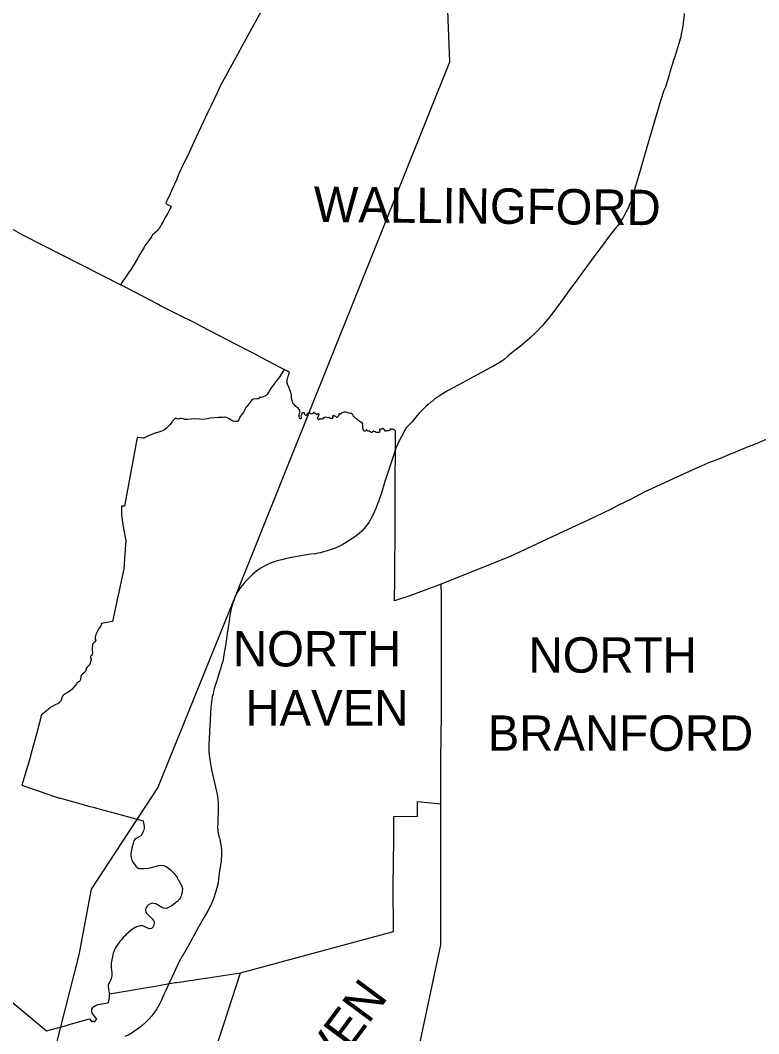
# Model space of a CAD drawing. Extents: x 0 to 2603, y -226 to 830.
# Drawn here: x 163.93 to 192.1, y 536.34 to 575 of the extents above; entities that cross this region are included whole.
import ezdxf

# ---------------------------------------------------------------- set-up
doc = ezdxf.new("R2010")
doc.units = 0
for name, color, linetype in [('CT_TSH_Map_Districts', 7, 'Continuous'), ('CT_TSH_Map_Interstate_Roads', 7, 'Continuous'), ('CT_TSH_Map_Town_Limits', 7, 'Continuous'), ('CT_TSH_Map_Town_Text', 7, 'Continuous'), ('CT_TSH_Map_US_and_State_Routes', 7, 'Continuous')]:
    doc.layers.add(name, color=color, linetype=linetype)

msp = doc.modelspace()

# ---------------------------------------------------------------- linework, layer by layer
at = {"layer": 'CT_TSH_Map_Districts'}
for points in [[(173.233, 575.543), (172.476, 574.159), (172.221, 573.694), (171.56, 572.484), (171.449, 572.255), (171.196, 571.72), (171.085, 571.492), (170.547, 570.342), (170.371, 569.958), (170.259, 569.712), (170.163, 569.522), (169.98, 569.133), (169.95, 569.088), (169.948, 569.08), (169.885, 568.911), (169.81, 568.745), (169.735, 568.578), (169.645, 568.377), (169.54, 568.136), (169.502, 568.052), (169.487, 568.006), (169.576, 567.958), (169.669, 567.907), (169.691, 567.885), (169.614, 567.745), (169.574, 567.663), (169.546, 567.619), (169.518, 567.581), (169.463, 567.478), (169.405, 567.37), (169.323, 567.217), (169.285, 567.144), (169.259, 567.104), (169.235, 567.063), (169.219, 567.041), (169.197, 567.017), (169.169, 566.978), (169.125, 566.935), (169.045, 566.871), (169.009, 566.84), (168.978, 566.813), (168.945, 566.758), (168.837, 566.602), (168.744, 566.483), (168.684, 566.387), (168.644, 566.318), (168.578, 566.21), (168.496, 566.071), (168.405, 565.913), (168.28, 565.693), (168.162, 565.506), (168.058, 565.359), (167.952, 565.205), (167.881, 565.096), (167.829, 565.027), (167.807, 564.99), (167.785, 564.951), (167.779, 564.932), (167.77, 564.908), (167.768, 564.9)], [(163.306, 567.224), (164.016, 566.811), (165.545, 566.034), (167.768, 564.9)]]:
    msp.add_lwpolyline(points, dxfattribs=at)
at = {"layer": 'CT_TSH_Map_Interstate_Roads'}
for p, q in [((189.167, 574.582), (189.157, 574.531)), ((187.871, 570.279), (187.654, 569.539)), ((183.012, 562.568), (182.68, 562.318)), ((179.946, 560.69), (179.877, 560.645)), ((179.073, 559.925), (178.883, 559.677)), ((179.145, 560.01), (179.073, 559.925)), ((178.883, 559.677), (178.655, 559.453)), ((174.356, 554.519), (174.287, 554.506)), ((174.78, 554.589), (174.356, 554.519)), ((171.929, 552.293), (171.893, 552.077)), ((171.547, 550.197), (171.41, 549.761)), ((171.564, 550.252), (171.547, 550.197)), ((171.233, 549.076), (171.207, 548.894)), ((171.149, 547.889), (171.131, 547.561)), ((170.948, 540.793), (170.759, 540.456)), ((168.474, 536.57), (168.438, 536.542))]:
    msp.add_line(p, q, dxfattribs=at)
for points in [[(189.25, 575.254), (189.251, 575.203), (189.234, 575.008), (189.203, 574.777), (189.167, 574.582)], [(189.157, 574.531), (189.109, 574.309), (189.086, 574.239)], [(189.086, 574.239), (188.881, 573.557), (188.853, 573.497)], [(188.853, 573.497), (188.825, 573.383), (188.763, 573.185), (188.708, 573.012)], [(188.708, 573.012), (188.678, 572.909), (188.537, 572.445)], [(188.537, 572.445), (188.483, 572.315), (188.355, 571.926), (187.871, 570.279)], [(187.654, 569.539), (187.521, 569.082), (187.398, 568.668), (187.277, 568.245), (187.227, 568.101), (187.161, 567.937), (187.101, 567.8), (187.044, 567.688), (186.981, 567.572), (186.912, 567.453)], [(186.912, 567.453), (186.845, 567.347), (186.813, 567.3), (186.732, 567.186), (186.64, 567.063), (186.544, 566.947), (186.498, 566.893), (186.398, 566.759), (186.126, 566.391), (185.853, 566.022), (185.569, 565.64), (185.395, 565.403)], [(185.395, 565.403), (185.355, 565.35), (185.093, 564.996)], [(185.093, 564.996), (184.923, 564.767), (184.469, 564.147)], [(184.469, 564.147), (184.347, 563.975), (184.248, 563.839), (184.06, 563.598), (183.847, 563.354), (183.613, 563.104), (183.367, 562.872), (183.194, 562.719), (183.012, 562.568)], [(182.68, 562.318), (182.609, 562.249), (182.531, 562.182), (182.385, 562.063), (182.262, 561.975), (182.131, 561.89), (181.987, 561.809), (181.81, 561.719), (181.686, 561.655), (181.199, 561.387), (180.918, 561.237)], [(180.918, 561.237), (180.64, 561.085), (180.227, 560.861)], [(180.227, 560.861), (180.125, 560.801), (180.027, 560.738), (179.946, 560.69)], [(179.65, 560.474), (179.605, 560.442), (179.488, 560.343)], [(179.877, 560.645), (179.845, 560.619), (179.728, 560.539), (179.65, 560.474)], [(179.488, 560.343), (179.391, 560.256), (179.337, 560.202), (179.246, 560.107), (179.145, 560.01)], [(178.655, 559.453), (178.591, 559.348), (178.524, 559.216), (178.463, 559.1), (178.395, 558.975), (178.33, 558.841), (178.259, 558.674), (178.184, 558.438), (177.916, 557.636), (177.842, 557.402), (177.692, 556.925), (177.637, 556.755), (177.607, 556.663), (177.563, 556.554), (177.491, 556.379), (177.432, 556.234), (177.371, 556.096), (177.309, 555.984), (177.223, 555.847), (177.139, 555.728), (177.051, 555.618), (176.959, 555.516), (176.856, 555.421), (176.745, 555.331), (176.679, 555.288)], [(176.679, 555.288), (176.456, 555.137), (176.358, 555.076), (176.23, 555.006), (176.078, 554.929), (175.941, 554.868), (175.795, 554.81), (175.674, 554.77)], [(175.28, 554.668), (175.188, 554.651), (175.02, 554.628), (174.78, 554.589)], [(175.674, 554.77), (175.601, 554.748), (175.503, 554.719), (175.38, 554.688), (175.28, 554.668)], [(173.633, 554.34), (173.58, 554.324), (173.48, 554.287), (173.365, 554.243), (173.263, 554.193), (173.17, 554.14), (173.083, 554.087), (172.989, 554.019), (172.897, 553.944), (172.793, 553.853), (172.64, 553.709), (172.567, 553.638), (172.487, 553.554), (172.402, 553.456), (172.318, 553.344), (172.236, 553.214), (172.168, 553.089)], [(173.903, 554.422), (173.733, 554.373), (173.633, 554.34)], [(174.287, 554.506), (174.266, 554.504), (174.215, 554.494), (174.047, 554.458), (173.903, 554.422)], [(172.089, 552.898), (172.07, 552.859), (172.039, 552.778), (172.009, 552.688), (171.978, 552.567)], [(172.168, 553.089), (172.118, 552.984), (172.093, 552.919), (172.089, 552.898)], [(171.978, 552.567), (171.96, 552.483), (171.929, 552.293)], [(171.893, 552.077), (171.858, 551.851), (171.825, 551.605), (171.8, 551.422)], [(171.8, 551.422), (171.771, 551.229), (171.702, 550.793), (171.674, 550.616), (171.655, 550.545), (171.623, 550.451), (171.591, 550.368), (171.564, 550.252)], [(171.41, 549.761), (171.366, 549.623), (171.326, 549.5), (171.302, 549.399), (171.285, 549.299), (171.268, 549.259), (171.257, 549.192)], [(171.207, 548.894), (171.194, 548.777), (171.186, 548.602), (171.169, 548.28)], [(171.257, 549.192), (171.238, 549.092), (171.233, 549.076)], [(171.169, 548.28), (171.16, 548.102), (171.149, 547.889)], [(171.131, 547.561), (171.121, 547.39), (171.121, 547.277), (171.124, 547.134)], [(171.124, 547.134), (171.136, 546.965), (171.159, 546.79), (171.208, 546.482), (171.277, 546.184)], [(171.277, 546.184), (171.312, 546.026), (171.376, 545.749), (171.418, 545.576), (171.45, 545.405), (171.466, 545.278), (171.477, 545.147), (171.483, 544.963), (171.477, 544.796), (171.468, 544.549), (171.462, 544.359), (171.458, 544.231), (171.468, 544.085)], [(171.468, 544.085), (171.483, 543.992), (171.498, 543.934), (171.524, 543.838), (171.526, 543.818)], [(171.526, 543.818), (171.553, 543.713), (171.574, 543.596), (171.59, 543.479), (171.603, 543.322), (171.607, 543.191)], [(171.607, 543.191), (171.606, 543.111), (171.6, 543.021), (171.591, 542.902), (171.573, 542.779), (171.558, 542.696)], [(171.558, 542.696), (171.531, 542.553), (171.509, 542.363)], [(171.509, 542.363), (171.497, 542.248), (171.475, 542.104)], [(171.475, 542.104), (171.43, 541.904), (171.383, 541.724), (171.318, 541.527), (171.211, 541.274), (171.082, 541.034), (170.948, 540.793)], [(170.759, 540.456), (170.424, 539.852), (170.129, 539.327), (170.111, 539.305)], [(170.111, 539.305), (169.99, 539.101), (169.786, 538.652), (169.599, 538.245)], [(169.599, 538.245), (169.496, 538.014), (169.413, 537.843), (169.332, 537.659)], [(169.332, 537.659), (169.305, 537.594), (169.238, 537.465), (169.138, 537.295), (169.025, 537.132)], [(168.848, 536.916), (168.8, 536.864), (168.704, 536.769)], [(169.025, 537.132), (168.947, 537.031), (168.848, 536.916)], [(168.438, 536.542), (168.306, 536.451), (168.203, 536.383), (168.043, 536.292), (167.925, 536.239)], [(168.704, 536.769), (168.583, 536.659), (168.474, 536.57)]]:
    msp.add_lwpolyline(points, dxfattribs=at)
at = {"layer": 'CT_TSH_Map_Town_Limits'}
for points in [[(173.233, 575.543), (172.476, 574.159), (172.221, 573.694), (171.56, 572.484), (171.449, 572.255), (171.196, 571.72), (171.085, 571.492), (170.547, 570.342), (170.371, 569.958), (170.259, 569.712), (170.163, 569.522), (169.98, 569.133), (169.95, 569.088), (169.948, 569.08), (169.885, 568.911), (169.81, 568.745), (169.735, 568.578), (169.645, 568.377), (169.54, 568.136), (169.502, 568.052), (169.487, 568.006), (169.576, 567.958), (169.669, 567.907), (169.691, 567.885), (169.614, 567.745), (169.574, 567.663), (169.546, 567.619), (169.518, 567.581), (169.463, 567.478), (169.405, 567.37), (169.323, 567.217), (169.285, 567.144), (169.259, 567.104), (169.235, 567.063), (169.219, 567.041), (169.197, 567.017), (169.169, 566.978), (169.125, 566.935), (169.045, 566.871), (169.009, 566.84), (168.978, 566.813), (168.945, 566.758), (168.837, 566.602), (168.744, 566.483), (168.684, 566.387), (168.644, 566.318), (168.578, 566.21), (168.496, 566.071), (168.405, 565.913), (168.28, 565.693), (168.162, 565.506), (168.058, 565.359), (167.952, 565.205), (167.881, 565.096), (167.829, 565.027), (167.807, 564.99), (167.785, 564.951), (167.779, 564.932), (167.77, 564.908), (167.768, 564.9)], [(163.306, 567.224), (164.016, 566.811), (165.545, 566.034), (167.768, 564.9)], [(174.001, 561.672), (173.819, 561.768), (173.627, 561.87), (173.115, 562.137), (172.86, 562.27), (172.658, 562.378), (172.161, 562.632), (170.847, 563.317), (170.706, 563.394), (170.613, 563.439), (169.942, 563.775), (169.278, 564.104), (169.147, 564.177), (167.768, 564.9)], [(174.001, 561.672), (173.834, 561.41), (173.741, 561.292), (173.688, 561.226), (173.505, 560.976), (173.455, 560.889), (173.388, 560.792), (173.349, 560.727), (173.329, 560.703), (173.285, 560.677), (173.169, 560.622), (173.106, 560.612), (173.074, 560.612), (173.056, 560.614), (173.048, 560.592), (173.018, 560.564), (172.958, 560.554), (172.811, 560.544), (172.771, 560.526), (172.662, 560.378), (172.619, 560.325), (172.588, 560.275), (172.551, 560.235), (172.445, 560.043), (172.337, 559.901), (172.312, 559.856), (172.275, 559.797), (172.244, 559.702), (172.226, 559.689), (172.169, 559.69), (172.144, 559.694), (172.114, 559.692), (172.06, 559.706), (171.993, 559.737), (171.904, 559.794), (171.829, 559.832), (171.752, 559.855), (171.719, 559.857), (171.663, 559.85), (171.478, 559.84), (171.191, 559.821), (171.063, 559.789), (170.915, 559.775), (170.772, 559.776), (170.578, 559.793), (170.447, 559.788), (170.327, 559.773), (170.214, 559.772), (170.153, 559.79), (170.069, 559.803), (170.042, 559.809), (169.981, 559.796), (169.947, 559.787), (169.937, 559.781), (169.896, 559.802), (169.829, 559.811), (169.816, 559.781), (169.79, 559.751), (169.736, 559.701), (169.644, 559.585), (169.51, 559.441), (169.437, 559.381), (169.352, 559.332), (169.297, 559.312), (169.077, 559.244), (168.853, 559.161), (168.649, 559.063), (168.613, 559.056), (168.5, 559.07), (168.433, 559.083), (168.392, 559.087), (167.902, 556.458), (167.791, 556.466), (167.792, 556.419), (167.793, 556.291), (167.797, 556.139), (167.843, 555.758), (167.897, 555.488), (167.954, 555.139), (167.929, 554.825), (167.885, 554.08), (167.455, 552.07), (167.019, 551.987), (167.026, 551.973), (167.018, 551.934), (167.002, 551.903), (166.926, 551.796), (166.833, 551.626), (166.818, 551.576), (166.807, 551.512), (166.792, 551.47), (166.785, 551.411), (166.792, 551.392), (166.809, 551.364), (166.809, 551.349), (166.771, 551.289), (166.691, 551.202), (166.692, 551.137), (166.671, 551.084), (166.668, 551.029), (166.673, 550.995)], [(174.345, 560.37), (174.326, 560.411), (174.315, 560.454), (174.308, 560.496), (174.279, 560.573), (174.272, 560.654), (174.278, 560.71), (174.27, 560.754), (174.242, 560.855), (174.217, 560.893), (174.207, 560.907), (174.172, 561.009), (174.127, 561.117), (174.104, 561.204), (174.108, 561.247), (174.122, 561.334), (174.131, 561.359), (174.164, 561.458), (174.205, 561.572), (174.001, 561.672)], [(176.088, 559.982), (176.085, 559.941), (176.082, 559.928), (176.043, 559.882), (176.032, 559.859), (176.018, 559.852), (176.006, 559.852), (175.965, 559.89), (175.947, 559.897), (175.909, 559.899), (175.863, 559.916), (175.854, 559.913), (175.843, 559.891), (175.844, 559.825), (175.837, 559.813), (175.83, 559.807), (175.813, 559.804), (175.778, 559.807), (175.76, 559.814), (175.724, 559.846), (175.696, 559.851), (175.68, 559.838), (175.658, 559.836), (175.606, 559.846), (175.566, 559.858), (175.552, 559.857), (175.518, 559.832), (175.499, 559.828), (175.463, 559.785), (175.438, 559.778), (175.397, 559.792), (175.379, 559.778), (175.369, 559.777), (175.352, 559.79), (175.336, 559.788), (175.316, 559.761), (175.303, 559.756), (175.289, 559.759), (175.279, 559.776), (175.272, 559.803), (175.273, 559.823), (175.297, 559.858), (175.303, 559.895), (175.315, 559.922), (175.316, 559.931), (175.328, 559.946), (175.325, 559.98), (175.303, 559.986), (175.279, 559.982), (175.245, 559.952), (175.236, 559.951), (175.213, 559.97), (175.162, 560.016), (175.131, 560.031), (175.116, 560.033), (175.104, 560.027), (175.1, 560.006), (175.093, 559.999), (175.061, 559.98), (175.03, 559.975), (175.012, 559.984), (174.994, 560.008), (174.981, 560.017), (174.945, 560.014), (174.9, 559.999), (174.871, 559.992), (174.865, 559.978), (174.87, 559.937), (174.865, 559.923), (174.847, 559.916), (174.815, 559.936), (174.78, 559.945), (174.764, 559.976), (174.778, 559.987), (174.777, 560.018), (174.77, 560.024), (174.756, 560.024), (174.741, 560.018), (174.724, 560.019), (174.704, 560.032), (174.683, 560.025), (174.67, 560.004), (174.661, 559.946), (174.636, 559.9), (174.643, 559.864), (174.652, 559.835), (174.646, 559.812), (174.632, 559.797), (174.626, 559.789), (174.595, 559.812), (174.585, 559.825), (174.571, 559.874), (174.563, 559.964), (174.59, 560.041), (174.589, 560.097), (174.58, 560.143), (174.533, 560.206), (174.483, 560.244), (174.441, 560.26), (174.385, 560.327), (174.345, 560.37)], [(179.988, 553.492), (179.342, 553.253), (178.752, 553.037), (178.209, 552.85), (178.205, 553.065), (178.214, 553.487), (178.22, 554.298), (178.232, 555.217), (178.231, 556.693), (178.235, 557.133), (178.233, 557.662), (178.24, 558.395), (178.242, 558.895), (178.242, 559.334), (178.217, 559.352), (178.214, 559.361), (178.192, 559.378), (178.171, 559.385), (178.162, 559.392), (178.133, 559.404), (178.054, 559.401), (178.044, 559.399), (178.033, 559.382), (178.031, 559.365), (177.975, 559.341), (177.92, 559.338), (177.91, 559.331), (177.883, 559.32), (177.856, 559.323), (177.822, 559.371), (177.785, 559.412), (177.773, 559.425), (177.755, 559.42), (177.74, 559.4), (177.731, 559.411), (177.728, 559.43), (177.718, 559.429), (177.699, 559.403), (177.672, 559.407), (177.657, 559.409), (177.639, 559.393), (177.635, 559.376), (177.641, 559.339), (177.645, 559.317), (177.635, 559.29), (177.619, 559.277), (177.562, 559.269), (177.52, 559.276), (177.494, 559.276), (177.482, 559.302), (177.44, 559.317), (177.423, 559.325), (177.405, 559.322), (177.381, 559.304), (177.359, 559.304), (177.348, 559.273), (177.341, 559.271), (177.301, 559.284), (177.279, 559.293), (177.249, 559.322), (177.193, 559.325), (177.169, 559.342), (177.144, 559.371), (177.128, 559.374), (177.119, 559.366), (177.112, 559.349), (177.083, 559.324), (177.057, 559.324), (177.039, 559.337), (177.021, 559.36), (177.003, 559.434), (177.002, 559.554), (177.004, 559.585), (176.996, 559.61), (176.971, 559.642), (176.933, 559.666), (176.906, 559.674), (176.852, 559.71), (176.835, 559.728), (176.793, 559.762), (176.769, 559.799), (176.721, 559.826), (176.665, 559.867), (176.648, 559.887), (176.636, 559.9), (176.619, 559.946), (176.597, 559.97), (176.543, 560.006), (176.521, 560.012), (176.49, 560.004), (176.453, 560.013), (176.439, 560.019), (176.365, 560.052), (176.284, 560.049), (176.249, 560.04), (176.184, 560.012), (176.172, 559.996), (176.143, 559.977), (176.123, 559.977), (176.104, 559.987), (176.088, 559.982)], [(192.582, 559.09), (192.004, 558.841), (191.573, 558.673), (191.126, 558.485), (191.01, 558.443), (190.597, 558.271), (190.495, 558.236), (190.366, 558.182), (190.248, 558.14), (190.017, 558.042), (189.949, 558.019), (189.695, 557.896), (188.974, 557.568), (188.034, 557.137), (187.759, 557.012), (187.735, 556.996), (187.231, 556.737), (186.725, 556.492), (186.705, 556.478), (186.465, 556.353), (186.147, 556.203), (185.668, 555.962), (185.596, 555.926), (184.492, 555.417), (184.444, 555.398), (184.385, 555.376), (183.432, 554.929), (182.755, 554.613), (182.647, 554.56), (181.888, 554.25), (180.207, 553.576), (179.988, 553.492)], [(179.973, 545.11), (179.973, 546.659), (179.98, 547.8), (180.004, 548.4), (179.996, 548.54), (180.001, 551.935), (179.997, 552.305), (179.998, 553.039), (179.988, 553.492)], [(166.673, 550.995), (166.68, 550.856), (166.667, 550.792), (166.655, 550.77), (166.628, 550.744), (166.611, 550.717), (166.607, 550.698), (166.615, 550.675), (166.638, 550.639), (166.638, 550.606), (166.595, 550.477), (166.568, 550.411), (166.524, 550.36), (166.471, 550.312), (166.449, 550.279), (166.44, 550.252), (166.44, 550.234), (166.409, 550.149), (166.388, 550.127), (166.308, 550.061), (166.252, 550), (166.237, 549.969), (166.228, 549.852), (166.193, 549.783), (166.165, 549.759), (166.093, 549.709), (166.078, 549.694), (166.041, 549.64), (165.895, 549.478), (165.847, 549.433), (165.758, 549.368), (165.641, 549.306), (165.596, 549.267), (165.543, 549.212), (165.511, 549.153), (165.486, 549.059), (165.462, 549.011), (165.438, 548.983), (165.366, 548.93), (165.294, 548.9), (165.147, 548.828), (165.107, 548.805), (165.075, 548.779), (165.013, 548.721), (164.921, 548.649), (164.775, 548.531), (164.743, 548.512), (164.564, 547.82), (164.335, 546.998), (164.294, 546.834), (164.068, 546.076), (163.995, 545.826), (165.238, 545.397), (165.427, 545.323), (165.465, 545.327), (166.154, 545.136), (166.494, 545.038), (166.711, 544.99), (166.985, 544.912), (167.554, 544.752), (167.914, 544.657), (168.613, 544.464), (168.656, 544.239), (168.655, 544.186), (168.641, 544.103), (168.608, 544.027), (168.563, 543.941), (168.527, 543.891), (168.444, 543.844), (168.357, 543.792), (168.305, 543.746), (168.269, 543.702), (168.25, 543.648), (168.188, 543.425), (168.153, 543.219), (168.154, 543.129), (168.159, 543.065), (168.186, 542.965), (168.239, 542.871), (168.336, 542.728), (168.379, 542.694), (168.434, 542.663), (168.496, 542.646), (168.628, 542.64), (168.662, 542.64), (168.809, 542.657), (168.936, 542.687), (169.032, 542.715), (169.202, 542.758), (169.253, 542.766), (169.393, 542.755), (169.471, 542.73), (169.57, 542.666), (169.676, 542.577), (169.781, 542.48), (169.893, 542.339), (169.911, 542.307), (169.923, 542.25), (169.937, 542.233), (169.959, 542.208), (169.968, 542.197)], [(172.331, 538.662), (175.43, 539.503), (178.172, 540.245), (178.153, 541.992), (178.174, 543.738), (178.185, 544.624), (179.085, 544.645), (179.083, 545.204), (179.973, 545.11)], [(178.85, 534.429), (178.87, 534.538), (179.241, 536.265), (179.978, 539.735), (179.975, 541.521), (179.973, 543.992), (179.973, 545.11)], [(169.968, 542.197), (169.986, 542.172), (170.004, 542.142), (170.033, 542.092), (170.058, 542.041), (170.081, 541.994), (170.092, 541.957), (170.103, 541.93), (170.11, 541.909), (170.113, 541.887), (170.114, 541.855), (170.113, 541.813), (170.11, 541.791), (170.106, 541.732), (170.097, 541.692), (170.087, 541.654), (170.078, 541.624), (170.06, 541.58), (170.044, 541.552), (170.024, 541.512), (170.006, 541.48), (169.97, 541.439), (169.949, 541.412), (169.937, 541.398), (169.926, 541.388), (169.918, 541.387), (169.909, 541.387), (169.856, 541.339), (169.709, 541.226), (169.642, 541.181), (169.539, 541.13), (169.498, 541.123), (169.394, 541.133), (169.334, 541.156), (169.099, 541.292), (169.03, 541.316), (168.965, 541.32), (168.901, 541.303), (168.83, 541.267), (168.755, 541.197), (168.732, 541.16), (168.715, 541.114), (168.712, 541.056), (168.721, 541.007), (168.751, 540.941), (168.78, 540.904), (168.958, 540.731), (169.014, 540.661), (169.038, 540.606), (169.042, 540.562), (169.024, 540.486), (168.993, 540.413), (168.935, 540.355), (168.89, 540.346), (168.851, 540.347), (168.662, 540.439), (168.593, 540.461), (168.523, 540.461), (168.468, 540.45), (168.366, 540.423), (168.211, 540.335), (168.16, 540.299), (167.97, 540.124), (167.942, 540.089), (167.858, 540.011), (167.802, 539.94), (167.727, 539.858), (167.629, 539.726), (167.55, 539.606), (167.496, 539.471), (167.47, 539.414), (167.456, 539.356), (167.402, 539.031), (167.392, 538.871), (167.426, 538.648), (167.423, 538.561), (167.414, 538.486), (167.384, 538.4), (167.294, 538.23), (167.283, 538.201), (167.297, 538.019), (167.334, 537.87)], [(167.334, 537.87), (169.006, 538.149), (169.844, 538.292), (169.905, 538.303), (170.74, 538.419), (171.335, 538.513), (172.331, 538.662)], [(171.359, 535.685), (172.331, 538.662)], [(163.304, 537.809), (164.93, 536.448), (165.69, 536.659), (165.726, 536.673), (165.801, 536.692), (166.57, 536.911), (166.656, 536.794), (166.716, 536.84), (166.761, 536.801), (166.854, 536.897), (166.69, 537.118), (166.666, 537.18), (166.662, 537.217), (166.663, 537.276), (166.697, 537.341), (166.734, 537.378), (166.8, 537.416), (166.906, 537.459), (167.121, 537.502), (167.264, 537.525), (167.292, 537.538), (167.313, 537.584), (167.327, 537.644), (167.336, 537.765), (167.334, 537.87)]]:
    msp.add_lwpolyline(points, dxfattribs=at)
at = {"layer": 'CT_TSH_Map_US_and_State_Routes'}
msp.add_lwpolyline([(164.946, 534.505), (166.172, 539.356), (166.653, 541.86), (169.173, 545.726), (172.168, 553.089), (180.318, 573.415), (180.169, 577.311)], dxfattribs=at)

# ---------------------------------------------------------------- texts
at = {"layer": 'CT_TSH_Map_Town_Text'}
for s, rotation, p in [('WALLINGFORD', 359.4215, (175.117, 567.307)), ('EAST HAVEN', 53.3505, (171.162, 528.557))]:
    msp.add_text(s, height=1.35, rotation=rotation, dxfattribs=at).set_placement(p)
for s, p in [('NORTH', (172.043, 550.351)), ('NORTH', (183.318, 550.113)), ('HAVEN', (172.516, 548.099)), ('BRANFORD', (181.759, 547.133))]:
    msp.add_text(s, height=1.35, dxfattribs=at).set_placement(p)

doc.saveas('drawing.dxf')
